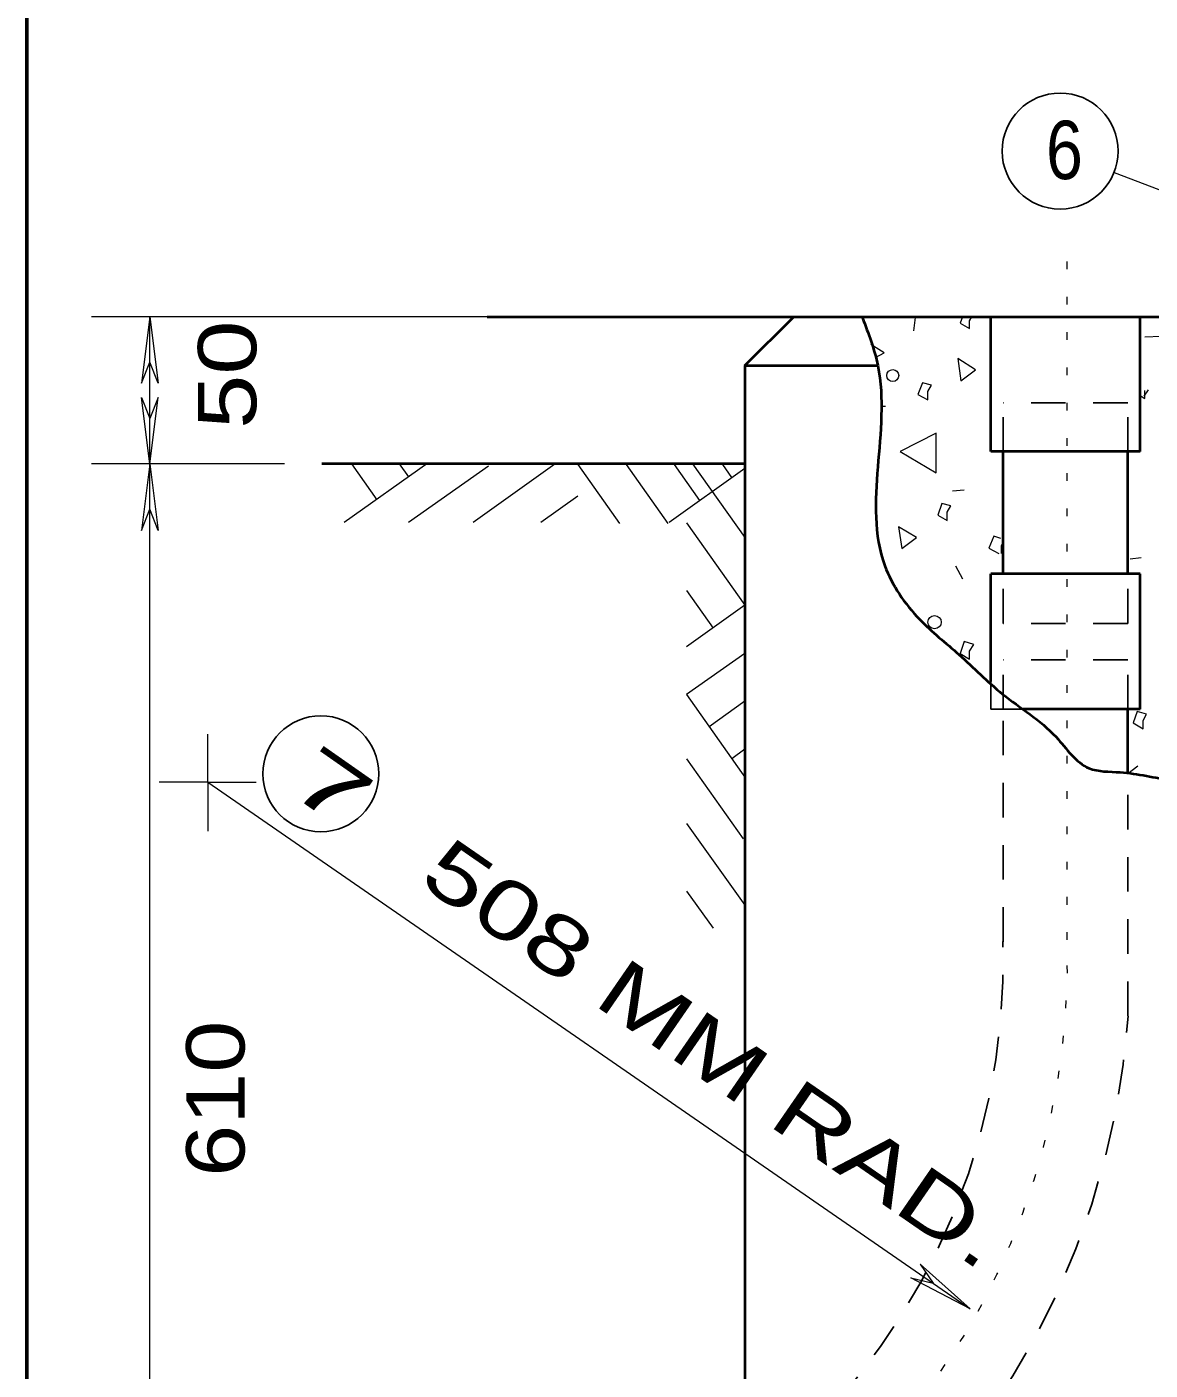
# Model space of a CAD drawing. Extents: x 312583 to 312854, y 144419 to 144597.
# Drawn here: x 312718.86 to 312733.5, y 144451.76 to 144469.26 of the extents above; entities that cross this region are included whole.
import ezdxf

# ---------------------------------------------------------------- set-up
doc = ezdxf.new("R2010")
doc.units = 0
doc.header["$LTSCALE"] = 0.3
doc.linetypes.add('DOTTED', pattern=[1.5, 0.3, -1.2])
doc.linetypes.add('SHORT_DASHED', pattern=[2.7, 1.5, -1.2])
doc.layers.add('1', color=7, linetype='Continuous', lineweight=25)
doc.layers.add('2', color=7, linetype='Continuous', lineweight=13)

msp = doc.modelspace()

# ---------------------------------------------------------------- linework, layer by layer
at = {"layer": '1', "lineweight": 53}
msp.add_line((312718.861, 144423.0846), (312718.861, 144506.4889), dxfattribs=at)
at = {"layer": '1', "linetype": 'DOTTED', "lineweight": 13}
msp.add_line((312732.4216, 144457.3678), (312732.4216, 144466.2075), dxfattribs=at)
at = {"layer": '1', "lineweight": 40}
for p, q in [((312724.8622, 144465.4868), (312790.0289, 144465.4868)), ((312728.2202, 144464.8505), (312728.8566, 144465.4868)), ((312728.8566, 144465.4868), (312794.0232, 144465.4868)), ((312731.4249, 144463.7311), (312731.4249, 144465.4868)), ((312733.3722, 144463.7311), (312733.3722, 144465.4868)), ((312728.2202, 144464.8505), (312728.2202, 144442.4868)), ((312728.2202, 144464.8505), (312729.9529, 144464.8505)), ((312733.3722, 144463.7311), (312731.4249, 144463.7311)), ((312731.5859, 144462.1365), (312731.5859, 144463.7311)), ((312733.2112, 144462.1365), (312733.2112, 144463.7311)), ((312728.2202, 144463.5701), (312722.7079, 144463.5701)), ((312733.3722, 144462.1365), (312731.4249, 144462.1365)), ((312731.4249, 144460.7335), (312731.4249, 144462.1365)), ((312733.3722, 144460.3731), (312733.3722, 144462.1365)), ((312733.3722, 144460.3731), (312731.8466, 144460.3731)), ((312733.2112, 144459.5375), (312733.2112, 144460.3731))]:
    msp.add_line(p, q, dxfattribs=at)
at = {"layer": '1', "linetype": 'SHORT_DASHED'}
for p, q in [((312733.2112, 144464.3675), (312731.5859, 144464.3675)), ((312731.5859, 144463.7311), (312731.5859, 144464.3675)), ((312733.2112, 144463.7311), (312733.2112, 144464.3675)), ((312731.5859, 144461.4925), (312731.5859, 144462.1365)), ((312733.2112, 144461.4925), (312733.2112, 144462.1365)), ((312733.2112, 144461.4925), (312731.5859, 144461.4925)), ((312733.2112, 144461.0171), (312731.5859, 144461.0171)), ((312733.2112, 144460.3731), (312733.2112, 144461.0171)), ((312733.2112, 144456.3788), (312733.2112, 144459.5375))]:
    msp.add_line(p, q, dxfattribs=at)
for points in [[(312731.5859, 144457.3448), (312731.5859, 144460.3731), (312731.5859, 144461.0171)], [(312731.8466, 144460.3731), (312731.4249, 144460.3731), (312731.4249, 144460.7335)]]:
    msp.add_lwpolyline(points, dxfattribs=at)
at = {"layer": '1', "linetype": 'DOTTED', "lineweight": 13}
msp.add_arc((312722.8929, 144457.0978), 9.5322, 276.07999, 1.63993, dxfattribs=at)
at = {"layer": '1', "linetype": 'SHORT_DASHED'}
for radius, start, end in [(8.6946, 307.77967, 1.64033), (10.3468, 300.9843, 355.99394)]:
    msp.add_arc((312722.8929, 144457.0978), radius, start, end, dxfattribs=at)
at = {"layer": '1', "lineweight": 40}
msp.add_spline([(312729.7536, 144465.4715), (312729.9529, 144464.8505), (312730.0449, 144462.2438), (312730.4972, 144461.5461), (312731.0109, 144461.0861), (312731.5782, 144460.5725), (312732.2759, 144460.0128), (312732.7052, 144459.6065), (312733.1116, 144459.5528), (312733.7862, 144459.4531), (312735.3886, 144459.4531), (312735.4729, 144459.4378)], degree=3, dxfattribs=at)
at = {"layer": '2'}
for p, q in [((312733.0349, 144467.3651), (312734.4072, 144466.8438)), ((312728.0056, 144465.4868), (312719.702, 144465.4868)), ((312720.4642, 144465.4868), (312720.3568, 144464.6205)), ((312720.4642, 144465.4868), (312720.5715, 144464.6205)), ((312730.4206, 144465.3028), (312730.4436, 144465.4791)), ((312731.1489, 144465.4331), (312731.1796, 144465.4868)), ((312733.4336, 144465.2261), (312733.6482, 144465.2338)), ((312720.3568, 144464.6205), (312720.4642, 144464.8965)), ((312720.5715, 144464.6205), (312720.4642, 144464.8965)), ((312720.3568, 144464.4365), (312720.4642, 144464.1605)), ((312720.4642, 144463.5701), (312720.3568, 144464.4365)), ((312720.5715, 144464.4365), (312720.4642, 144464.1605)), ((312720.4642, 144463.5701), (312720.5715, 144464.4365)), ((312733.4259, 144464.4518), (312733.4796, 144464.5361)), ((312730.0219, 144464.3215), (312730.0526, 144464.3215)), ((312722.2172, 144463.5701), (312719.702, 144463.5701)), ((312720.4642, 144463.5701), (312720.3568, 144462.7038)), ((312720.4642, 144463.5701), (312720.5715, 144462.7038)), ((312722.9992, 144462.8111), (312724.0879, 144463.5855)), ((312723.0912, 144463.5701), (312723.4209, 144463.1025)), ((312723.7122, 144463.5701), (312723.8349, 144463.4015)), ((312723.8349, 144462.8111), (312724.8776, 144463.5471)), ((312724.6782, 144462.8111), (312725.7439, 144463.5701)), ((312726.0429, 144463.5625), (312726.5872, 144462.7958)), ((312726.6716, 144463.5625), (312727.2159, 144462.7958)), ((312727.3002, 144463.5625), (312727.6299, 144463.0948)), ((312727.5379, 144463.5701), (312728.2202, 144462.6118)), ((312727.9289, 144463.5625), (312728.0439, 144463.3938)), ((312727.2312, 144462.8111), (312728.2202, 144463.5165)), ((312730.9266, 144463.2175), (312731.0799, 144463.2328)), ((312725.5599, 144462.8111), (312726.0429, 144463.1561)), ((312720.3568, 144462.7038), (312720.4642, 144462.9798)), ((312720.5715, 144462.7038), (312720.4642, 144462.9798)), ((312727.4612, 144462.8035), (312728.2202, 144461.7301)), ((312731.5629, 144462.5045), (312731.5859, 144462.5505)), ((312731.5629, 144462.4048), (312731.5629, 144462.5045)), ((312733.2419, 144462.3358), (312733.3876, 144462.3511)), ((312730.9649, 144462.2438), (312731.0569, 144462.0751)), ((312727.4612, 144461.9218), (312727.8062, 144461.4311)), ((312728.2202, 144461.7301), (312727.4612, 144461.1858)), ((312728.2202, 144461.1015), (312727.4612, 144460.5648)), ((312727.4612, 144460.5648), (312728.2279, 144459.4761)), ((312728.2202, 144460.4805), (312727.7526, 144460.1431)), ((312721.2206, 144459.4225), (312721.2206, 144460.0511)), ((312727.4612, 144459.7291), (312728.1972, 144458.6865)), ((312728.2202, 144459.8518), (312728.0516, 144459.7291)), ((312733.2112, 144459.5375), (312733.3416, 144459.6371)), ((312721.2206, 144459.4225), (312720.5842, 144459.4225)), ((312721.2206, 144459.4225), (312731.1566, 144452.5608)), ((312721.2206, 144459.4225), (312721.2206, 144458.7861)), ((312721.2206, 144459.4225), (312721.8492, 144459.4225)), ((312727.4612, 144458.8858), (312728.2202, 144457.8201)), ((312727.4612, 144458.0041), (312727.8062, 144457.5211)), ((312730.5049, 144453.1435), (312730.6736, 144452.8981)), ((312731.1566, 144452.5608), (312730.5049, 144453.1435)), ((312730.3822, 144452.9671), (312730.6736, 144452.8981)), ((312731.1566, 144452.5608), (312730.3822, 144452.9671))]:
    msp.add_line(p, q, dxfattribs=at)
for points in [[(312720.4642, 144448.4285), (312720.4642, 144463.5701), (312720.4642, 144465.4868)], [(312731.0569, 144465.4868), (312731.0262, 144465.4025), (312731.1489, 144465.3335), (312731.1489, 144465.4331)], [(312729.9222, 144464.9578), (312730.0372, 144465.0191), (312729.8609, 144465.1265)], [(312733.3722, 144464.4595), (312733.4336, 144464.4211), (312733.4336, 144464.5285)], [(312731.5552, 144462.5965), (312731.4632, 144462.6271), (312731.4019, 144462.4738), (312731.5322, 144462.4048)]]:
    msp.add_lwpolyline(points, dxfattribs=at)
for points in [[(312731.0339, 144464.6511), (312731.2256, 144464.7968), (312730.9956, 144464.9425)], [(312730.6046, 144464.5131), (312730.6506, 144464.5975), (312730.5356, 144464.6281), (312730.4742, 144464.4748), (312730.6046, 144464.4058)], [(312730.7119, 144463.4551), (312730.7119, 144463.9688), (312730.2442, 144463.7311)], [(312730.8576, 144462.9415), (312730.9036, 144463.0258), (312730.7886, 144463.0565), (312730.7349, 144462.9031), (312730.8576, 144462.8341)], [(312730.2672, 144462.4661), (312730.4589, 144462.6118), (312730.2212, 144462.7498)], [(312731.1489, 144461.1321), (312731.2026, 144461.2165), (312731.0799, 144461.2548), (312731.0262, 144461.1015), (312731.1489, 144461.0248)], [(312733.4106, 144460.2275), (312733.4566, 144460.3118), (312733.3339, 144460.3425), (312733.2802, 144460.1968), (312733.4106, 144460.1201)]]:
    msp.add_lwpolyline(points, close=True, dxfattribs=at)
at = {"layer": '2', "lineweight": 25}
for centre in [(312732.3289, 144467.6462), (312722.6926, 144459.533)]:
    msp.add_circle(centre, 0.7557, dxfattribs=at)
at = {"layer": '2'}
for centre, radius in [((312730.1473, 144464.7216), 0.0784), ((312730.6927, 144461.5089), 0.0865)]:
    msp.add_circle(centre, radius, dxfattribs=at)

# ---------------------------------------------------------------- texts
at = {"layer": '2', "width": 0.85}
msp.add_text('6', height=0.76, dxfattribs=at).set_placement((312732.1452, 144467.2814))
at = {"layer": '2'}
for s, rotation, width, p in [('50 ', 90, 1.25, (312721.8512, 144464.0263)), ('7', 325, 1.7, (312722.2214, 144459.3235)), ('508 MM RAD.   ', 325.387, 1.4, (312723.9458, 144458.1135)), ('610 ', 90, 1.2, (312721.6981, 144454.2824))]:
    msp.add_text(s, height=0.76, rotation=rotation, dxfattribs=dict(at, width=width)).set_placement(p)

doc.saveas('drawing.dxf')
